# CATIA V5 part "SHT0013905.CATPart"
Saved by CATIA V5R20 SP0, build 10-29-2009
Part number: SHT0013905
Bounding box of the stored display mesh (mm): x 603.32 to 810.951, y -967.609 to -463.211, z 445.851 to 1308.581
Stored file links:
  C:\Users\gongbo\Desktop\设变_1\设变数据1-富生\主驾\不带侧板\SHT0013905.CATPart
  C:\Users\gongbo\Desktop\设变_1\设变数据1-富生\副驾不带腰托\高头枕\SHT0012236.CATPart

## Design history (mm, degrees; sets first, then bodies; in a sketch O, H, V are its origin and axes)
Body1 (main body)
Body2 "SHT0013905_AllCATPart.1\\头枕主体管\\几何体.2"
  Solid1: solid without history
Body3 "SHT0013905_AllCATPart.1\\靠背钢管上横骨架\\产品2_AllCATPart.1\\ECAS-6805001.1\\靠背钢管上横骨架\\靠背骨架装配总成\\靠背骨架焊接总成\\靠背钢管上横骨架.1\\支撑管-方案一"
  Solid2 "实体.1": solid without history
Body4 "SHT0013905_AllCATPart.1\\靠背下支撑管\\零件几何体"
  Solid3 "实体.1": solid without history
Body5 "SHT0013905_AllCATPart.1\\靠背支撑板条1\\零件几何体"
  Solid4 "实体.1": solid without history
Body6 "SHT0013905_AllCATPart.1\\支撑框线1\\产品2_AllCATPart.1\\ECAS-6805001.1\\支撑框线1\\靠背骨架装配总成\\靠背骨架焊接总成\\支撑框线\\零件几何体"
  Solid5 "实体.1": solid without history
Body7 "SHT0013905_AllCATPart.1\\腰托上固定片1.1\\H4 主驾骨架_AllCATPart_AllCATPart.1\\H4 主驾骨架_AllCATPart.1\\H4B-6800000.1\\靠背骨架.1\\靠背上横管.1\\Body.3"
  Solid6 "实体.1": solid without history
Body8 "SHT0013905_AllCATPart.1\\腰托上固定片1.2\\H4 主驾骨架_AllCATPart_AllCATPart.1\\H4 主驾骨架_AllCATPart.1\\H4B-6800000.1\\靠背骨架.1\\靠背上横管.1\\Body.3"
  Solid7 "实体.1": solid without history
Body9 "SHT0013905_AllCATPart.1\\腰托下固定片2.1\\零件几何体"
  Solid8 "实体.1": solid without history
Body10 "SHT0013905_AllCATPart.1\\腰托下固定片2.2\\零件几何体"
  Solid9 "实体.1": solid without history
Body11 "SHT0013905_AllCATPart.1\\旋转轴固定板.1\\旋转轴固定板"
  Solid10 "实体.1": solid without history
Body12 "SHT0013905_AllCATPart.1\\侧翼左侧泡沫支撑钢丝\\零件几何体"
  Solid11 "实体.1": solid without history
Body13 "SHT0013905_AllCATPart.1\\侧翼右侧泡沫支撑钢丝\\零件几何体"
  Solid12 "实体.1": solid without history
Body14 "SHT0013905_AllCATPart.1\\靠背主体管焊接总成\\靠背主体管.1\\几何体.2"
  Solid13 "实体.1": solid without history
Body15 "SHT0013905_AllCATPart.1\\靠背主体管焊接总成\\靠背骨架内衬管.2\\零件几何体"
  Solid14 "实体.1": solid without history
Body16 "SHT0013905_AllCATPart.1\\靠背主体管焊接总成\\靠背骨架内衬管.2\\几何体.2"
  Solid15 "实体.1": solid without history
Body17 "SHT0013905_AllCATPart.1\\靠背主体管焊接总成\\靠背骨架内衬管.1\\零件几何体"
  Solid16 "实体.1": solid without history
Body18 "SHT0013905_AllCATPart.1\\靠背主体管焊接总成\\靠背骨架内衬管.1\\几何体.2"
  Solid17 "实体.1": solid without history
Body19 "SHT0013905_AllCATPart.1\\靠背主体管焊接总成\\焊接六角螺母.1\\H4A-主驾座椅\\Product1.1\\座框_AllCATPart.2\\焊接螺母2\\PartBody"
  Solid18 "实体.1": solid without history
Body20 "SHT0013905_AllCATPart.1\\靠背主体管焊接总成\\焊接六角螺母.2\\H4A-主驾座椅\\Product1.1\\座框_AllCATPart.2\\焊接螺母2\\PartBody"
  Solid19 "实体.1": solid without history
Body21 "SHT0013905_AllCATPart.1\\靠背主体管焊接总成\\焊接六角螺母.3\\H4A-主驾座椅\\Product1.1\\座框_AllCATPart.2\\焊接螺母2\\PartBody"
  Solid20 "实体.1": solid without history
Body22 "SHT0013905_AllCATPart.1\\靠背主体管焊接总成\\焊接六角螺母.4\\H4A-主驾座椅\\Product1.1\\座框_AllCATPart.2\\焊接螺母2\\PartBody"
  Solid21 "实体.1": solid without history
Body23 "SHT0013905_AllCATPart.1\\ECU固定板\\零件几何体"
  Solid22 "实体.1": solid without history
Body24 "SHT0013905_AllCATPart.1\\ECU固定板焊道.1\\零件几何体.1"
  Solid23 "实体.1": solid without history
Body25 "SHT0013905_AllCATPart.1\\ECU固定板焊道.1\\零件几何体.2"
  Solid24 "实体.1": solid without history
Body26 "零件1.1\\sht0012236.1\\SHT0012224_AllCATPart.1\\几何体.39"
  Solid25 "实体.1": solid without history
Body27 "ASSY-fujiaditouzhen(wuyaotuo)_AllCATPart.1\\SHT0010244-1.1\\头枕横衬板\\H4 升级副驾.1\\副驾背总成\\H4 升级靠背总成_AllCATPart.1\\靠背骨架总成.1\\头枕盒\\横梁.2"
  Solid26: solid without history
